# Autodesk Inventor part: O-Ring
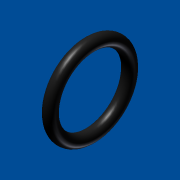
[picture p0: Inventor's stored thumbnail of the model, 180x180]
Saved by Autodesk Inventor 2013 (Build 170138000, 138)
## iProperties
Shininess: 41.0
Length Units: 11269
Angle Units: 11279
Time Units: 11290
Mass Units: 11283
Length Display Precision: 3
Angle Display Precision: 2
Created: 2001-04
Part Number: O-Ring
Material: Standard
Document SubType Name: Modellieren
Designer: dl
Density: 1 g/cm^3
Density: 0.0
Volumn: 0.0
Area: 0.0
PropertySet Name: Model Information
Control State: 0
Master: False
Checked Out: False
Author: dl
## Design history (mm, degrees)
body "Solid1"
revolve "Revolution1" stored, may be unused: angle "d1" = 90 deg
sketch "Sketch1"
  geometry: L1 (10.649, 8.004)-(7.512, 8.004); C1 r 1.25 at (9.228, 16.254)
  constraints: 2 end point, 1 centre point, 1 horizontal
  dimensions: "d0" = 2.5 diameter of C1; "d2" = 8.25 vertical distance of L1.start C1.centre
